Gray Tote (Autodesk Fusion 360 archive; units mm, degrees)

design "Gray Tote" references "Radio Power Module", "Air Volume Tank", "CIM Motor", "Spark Max Motor Controller", "Neo 550 Motor", "RedLine Motor", "squish wheel", "NI roboRIO", "Pnuematic Hub", "Compressor VIAIR", "Motor Megaplate", "Half Inch Hex Hub", "Bearing Megaplate", "Power Distribution Hub"
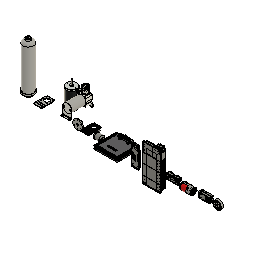
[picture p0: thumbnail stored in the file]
component_insert "Component Insert1"
component_insert "Component Insert2"
component_insert "Component Insert3"
component_insert "Component Insert4"
component_insert "Component Insert5"
component_insert "Component Insert6"
component_insert "Component Insert7"
component_insert "Component Insert8"
component_insert "Component Insert9"
component_insert "Component Insert10"
component_insert "Component Insert11"
component_insert "Component Insert12"
component_insert "Component Insert13"
component_insert "Component Insert14"

design "RedLine Motor"
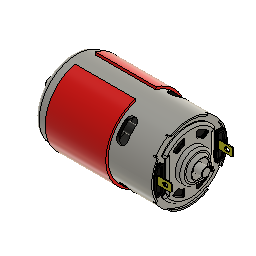
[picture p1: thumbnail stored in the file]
base_feature "Base Feature"

design "Power Distribution Hub"
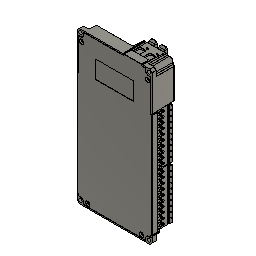
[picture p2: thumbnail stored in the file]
base_feature "Base Feature" bodies "Top Housing", "Bottom Housing", "Readout", "Screw (3)", "Screw (2)", "Screw (1)", "Screw", "Terminals (6)"
named bodies: "Top Housing", "Bottom Housing", "Readout", "Screw (3)", "Screw (2)", "Screw (1)", "Screw", "Terminals (6)", "USB C", "3 Pin (1)", "3 Pin", "Terminals (5)", "Terminals (4)", "Terminals (3)", "Terminals (2)", "Terminals (1)", "Terminals"

design "Pnuematic Hub"
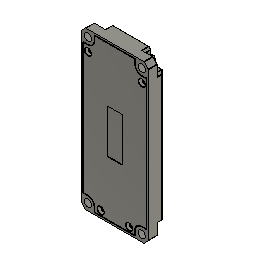
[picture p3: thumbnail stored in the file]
base_feature "Base Feature" bodies "Terminals (4)", "RS485 (1)", "RS485", "USB C", "Pin Connector", "Switch", "Terminals (2)", "Terminals (3)"
named bodies: "Terminals (4)", "RS485 (1)", "RS485", "USB C", "Pin Connector", "Switch", "Terminals (2)", "Terminals (3)", "Terminals", "Terminals (1)", "Outer Housing", "Bottom Housing", "Top Plate", "Screw", "Screw (1)", "Screw (2)", "Screw (3)"

design "CIM Motor"
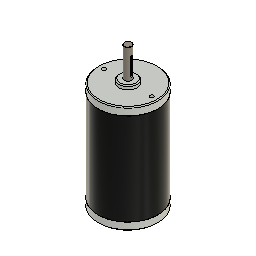
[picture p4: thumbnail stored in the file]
base_feature "Base Feature"

design "Neo 550 Motor"
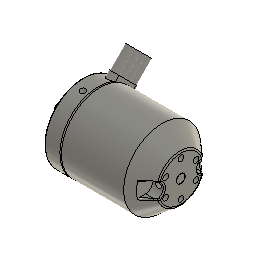
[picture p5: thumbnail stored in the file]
base_feature "Base Feature"

design "Compressor VIAIR"
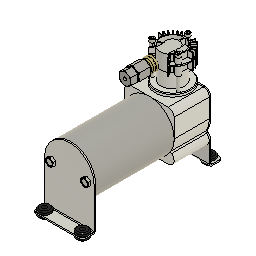
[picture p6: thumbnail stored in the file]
base_feature "Base Feature1"
base_feature "Base Feature1"
base_feature "Base Feature1"
base_feature "Base Feature1"
base_feature "Base Feature1"
base_feature "Base Feature1"
base_feature "Base Feature1"
base_feature "Base Feature1"
base_feature "Base Feature1"
base_feature "Base Feature1"
base_feature "Base Feature1"
as_built_joint "As-built1"
joint "Assemble1" alignAngle -180 alignOffsetX 0 alignOffsetY 0 alignOffsetZ 0
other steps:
create_component "CreateComponent1"
create_component "CreateComponent2"
create_component "CreateComponent3"
create_component "CreateComponent4"
create_component "CreateComponent5"
create_component "CreateComponent6"
create_component "CreateComponent7"
create_component "CreateComponent8"
create_component "CreateComponent9"
create_component "CreateComponent10"
create_component "CreateComponent11"
joint_origin "JointOrigin2"
joint_origin "JointOrigin2"

design "Half Inch Hex Hub"
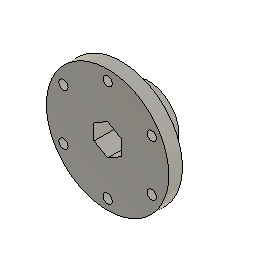
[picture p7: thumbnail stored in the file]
base_feature "Base Feature"

design "squish wheel"
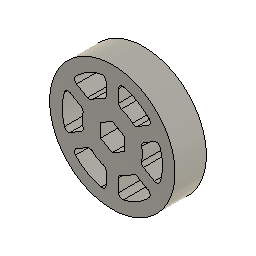
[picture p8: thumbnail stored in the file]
base_feature "Base Feature"

design "Bearing Megaplate"
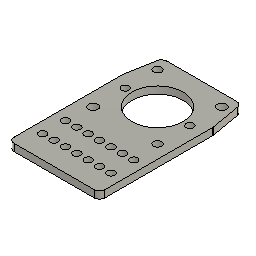
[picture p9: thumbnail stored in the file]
base_feature "Base Feature"

design "Motor Megaplate"
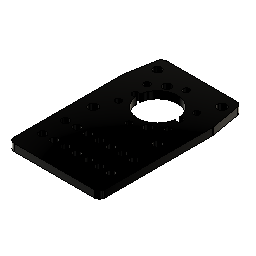
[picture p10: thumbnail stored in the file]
base_feature "Base Feature"

design "NI roboRIO"
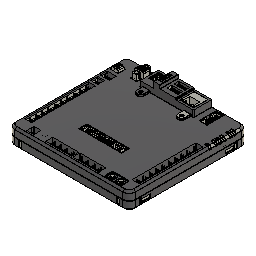
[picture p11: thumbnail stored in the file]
base_feature "Base Feature"

design "Spark Max Motor Controller"
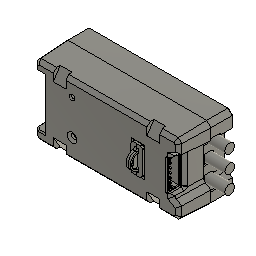
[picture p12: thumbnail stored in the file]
base_feature "Base Feature"

design "Radio Power Module"
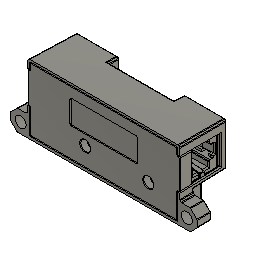
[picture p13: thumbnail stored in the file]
base_feature "Base Feature" bodies "Mid Plate", "Ethernet Port Cover (1)", "Ethernet Port (1)", "Ethernet Port Cover", "Ethernet Port", "Screw Terminal", "Screw Terminal (1)", "Retaining Piece"
named bodies: "Mid Plate", "Ethernet Port Cover (1)", "Ethernet Port (1)", "Ethernet Port Cover", "Ethernet Port", "Screw Terminal", "Screw Terminal (1)", "Retaining Piece", "Outer Housing", "Bottom Plate", "Top Plate", "Bottom Screw", "Bottom Screw (1)"

design "Air Volume Tank"
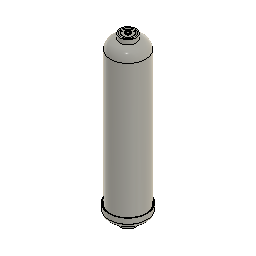
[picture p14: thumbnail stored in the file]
base_feature "Base Feature1"
base_feature "Base Feature1"
base_feature "Base Feature1"
base_feature "Base Feature1"
as_built_joint "As-built1"
joint "Assemble1" alignAngle 0 alignOffsetX 0 alignOffsetY 0 alignOffsetZ 0
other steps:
create_component "CreateComponent1"
create_component "CreateComponent2"
create_component "CreateComponent3"
create_component "CreateComponent4"
joint_origin "JointOrigin1"
joint_origin "JointOrigin1"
